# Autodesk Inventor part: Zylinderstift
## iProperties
Created: 2007-11
Part Number: Zylinderstift
Document SubType Name: Modeling
Designer: Benno
Manufacturer: Standard
Standards Organization: Custom
Author: Benno
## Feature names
1. Extrusion1
